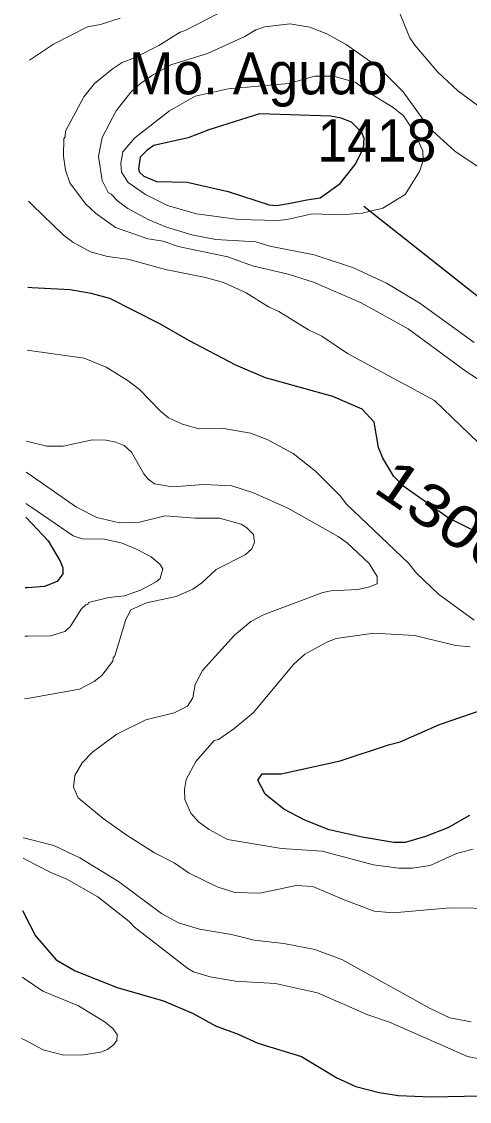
# Model space of a CAD drawing. Extents: x 598.3 to 623.2, y 6902.2 to 6930.1.
# Drawn here: x 598.405 to 599.256, y 6911.953 to 6914.004 of the extents above; entities that cross this region are included whole.
import ezdxf
from ezdxf.enums import TextEntityAlignment as Align

# ---------------------------------------------------------------- set-up
doc = ezdxf.new("R2010")
doc.units = 0
doc.header["$LTSCALE"] = 0.032
for name, color, linetype, lineweight in [('1', 7, 'Continuous', 25), ('2', 7, 'Continuous', 13), ('26', 7, 'Continuous', 25)]:
    doc.layers.add(name, color=color, linetype=linetype, lineweight=lineweight)
for name, color, linetype in [('21', 7, 'Continuous'), ('27', 7, 'Continuous'), ('61', 7, 'Continuous')]:
    doc.layers.add(name, color=color, linetype=linetype)

msp = doc.modelspace()

# ---------------------------------------------------------------- linework, layer by layer
at = {"layer": '1'}
msp.add_lwpolyline([(598.9122, 6913.6582), (598.9469, 6913.6651), (598.9727, 6913.6693), (599.0105, 6913.6961), (599.0387, 6913.7324), (599.0545, 6913.7632), (599.0563, 6913.7821), (599.0519, 6913.7933), (599.0322, 6913.8129), (599.0123, 6913.8205), (598.9919, 6913.8245), (598.8572, 6913.8285), (598.7607, 6913.798), (598.7215, 6913.7832), (598.6564, 6913.7686), (598.6433, 6913.7595), (598.6306, 6913.7464), (598.6274, 6913.724), (598.629, 6913.7176), (598.6374, 6913.7102), (598.6613, 6913.6999), (598.7199, 6913.699), (598.7976, 6913.6812), (598.8753, 6913.656), (598.8892, 6913.6545)], close=True, dxfattribs=at)
for points in [[(599.3331, 6913.0032), (599.2155, 6913.0611), (599.1295, 6913.1217), (599.1124, 6913.1398), (599.0918, 6913.1743), (599.0836, 6913.1948), (599.0748, 6913.2432), (599.0523, 6913.2675), (598.9967, 6913.2917), (598.8688, 6913.3274), (598.8122, 6913.3513), (598.7228, 6913.3978), (598.6676, 6913.4296), (598.5725, 6913.4779), (598.5373, 6913.4876), (598.4975, 6913.4942), (598.4242, 6913.4983), (598.4166, 6913.4987)], [(598.413, 6913.0626), (598.4244, 6913.0504), (598.4552, 6913.0173), (598.4784, 6912.9791), (598.4832, 6912.9661), (598.4832, 6912.9545), (598.4726, 6912.9405), (598.4485, 6912.9308), (598.4161, 6912.9284), (598.4119, 6912.9281)], [(599.2564, 6912.4958), (599.2148, 6912.4725), (599.1726, 6912.4555), (599.1343, 6912.4443), (599.1123, 6912.4443), (599.0523, 6912.4543), (598.9896, 6912.4686), (598.9432, 6912.4871), (598.9031, 6912.5076), (598.8682, 6912.5363), (598.8541, 6912.563), (598.8621, 6912.5745), (598.898, 6912.5747), (599.0104, 6912.5992), (599.1026, 6912.6302), (599.1246, 6912.6355), (599.1991, 6912.6687), (599.3027, 6912.7042)], [(598.4069, 6912.3154), (598.4206, 6912.2881), (598.4311, 6912.2671), (598.4706, 6912.2216), (598.5066, 6912.2003), (598.5865, 6912.1691), (598.6749, 6912.1433), (598.7312, 6912.1195), (598.7737, 6912.0959), (598.8164, 6912.0803), (598.8537, 6912.0632), (598.9367, 6912.0377), (599.0044, 6911.9972), (599.0404, 6911.9811), (599.0846, 6911.9694), (599.1214, 6911.9634), (599.1835, 6911.9611), (599.3103, 6911.9634)]]:
    msp.add_lwpolyline(points, dxfattribs=at)
at = {"layer": '2'}
for points in [[(598.9599, 6913.5091), (598.9117, 6913.5243), (598.844, 6913.5396), (598.7968, 6913.5567), (598.7027, 6913.5765), (598.674, 6913.5865), (598.6449, 6913.5914), (598.5834, 6913.6125), (598.5455, 6913.6401), (598.5263, 6913.6576), (598.4968, 6913.6976), (598.4881, 6913.7214), (598.4848, 6913.7482), (598.4849, 6913.782), (598.488, 6913.7851), (598.4881, 6913.7959), (598.523, 6913.8612), (598.5435, 6913.8864), (598.5771, 6913.9137), (598.596, 6913.9261), (598.6193, 6913.935), (598.6659, 6913.9587), (598.7064, 6913.9838), (598.7156, 6913.9867), (598.7997, 6914.0303)], [(599.1212, 6914.0256), (599.1427, 6913.9731), (599.1522, 6913.9589), (599.1963, 6913.9078), (599.2342, 6913.8724), (599.3103, 6913.8165)], [(598.592, 6914.0107), (598.5547, 6913.9985), (598.5303, 6913.9937), (598.4657, 6913.9613), (598.4258, 6913.9346), (598.4201, 6913.9308)], [(599.265, 6913.394), (599.1621, 6913.4687), (599.0987, 6913.507), (599.0359, 6913.536), (598.9608, 6913.5605), (598.877, 6913.5775), (598.8501, 6913.5857), (598.7741, 6913.5898), (598.7287, 6913.5988), (598.6806, 6913.6135), (598.6458, 6913.6281), (598.6066, 6913.6491), (598.588, 6913.663), (598.5754, 6913.6762), (598.5695, 6913.679), (598.5583, 6913.7022), (598.5513, 6913.7475), (598.5578, 6913.7835), (598.5849, 6913.8345), (598.6128, 6913.8698), (598.6307, 6913.8864), (598.6538, 6913.9023), (598.6888, 6913.9215), (598.7582, 6913.9433), (598.8295, 6913.9757), (598.8504, 6913.9881), (598.8672, 6913.9937), (598.915, 6913.9994), (598.9527, 6913.9936)], [(598.9527, 6913.9936), (598.9854, 6913.9805), (599.0218, 6913.9603), (599.0844, 6913.9161), (599.1301, 6913.8704), (599.1787, 6913.8024), (599.2284, 6913.758), (599.3226, 6913.6942)], [(598.4179, 6913.6626), (598.4248, 6913.6559), (598.4846, 6913.598), (598.5024, 6913.585), (598.536, 6913.5663), (598.5685, 6913.5574), (598.6067, 6913.5523), (598.6786, 6913.5331), (598.7542, 6913.5176), (598.789, 6913.508), (598.8317, 6913.4888), (598.8745, 6913.4617), (598.8936, 6913.4533), (598.9503, 6913.4184), (598.9756, 6913.4066), (599.0244, 6913.3732), (599.1898, 6913.2843), (599.2724, 6913.2052)], [(599.3075, 6913.3015), (599.25, 6913.3389), (599.1397, 6913.4205), (599.0501, 6913.4698), (598.9599, 6913.5091)], [(599.2651, 6912.8668), (599.1971, 6912.9164), (599.1555, 6912.9562), (599.1402, 6912.9749), (599.0226, 6913.0874), (599.0103, 6913.103), (598.9636, 6913.1498), (598.9214, 6913.1832), (598.872, 6913.2099), (598.84, 6913.222), (598.7892, 6913.231), (598.7417, 6913.2303), (598.7086, 6913.2396), (598.6844, 6913.2514), (598.6691, 6913.2638), (598.6288, 6913.3047), (598.6075, 6913.3213), (598.5656, 6913.3473), (598.524, 6913.3646), (598.4242, 6913.3785), (598.4156, 6913.3797)], [(598.4142, 6913.2068), (598.4295, 6913.2031), (598.4528, 6913.1975), (598.4841, 6913.1972), (598.5397, 6913.2092), (598.5658, 6913.2084), (598.5839, 6913.2052), (598.5998, 6913.1987), (598.6141, 6913.1859), (598.637, 6913.1445), (598.6455, 6913.1344), (598.6575, 6913.1258), (598.6911, 6913.1203), (598.7514, 6913.1243), (598.8043, 6913.1218), (598.8456, 6913.1089), (598.9109, 6913.0796), (599.0065, 6913.0258), (599.0235, 6913.0137), (599.0658, 6912.9747), (599.0806, 6912.9499), (599.0805, 6912.9358), (599.0646, 6912.9292), (599.0441, 6912.925), (598.993, 6912.9226), (598.9773, 6912.9195), (598.8662, 6912.8777), (598.8408, 6912.8642), (598.8094, 6912.8385), (598.7489, 6912.771), (598.7351, 6912.7444), (598.7307, 6912.719), (598.72, 6912.7032), (598.6949, 6912.6905), (598.6409, 6912.6773), (598.5857, 6912.6501), (598.5404, 6912.6163), (598.5201, 6912.596), (598.5059, 6912.5719), (598.5035, 6912.5496), (598.5122, 6912.5294), (598.5602, 6912.4898), (598.6035, 6912.4592), (598.6578, 6912.425), (598.6951, 6912.4056), (598.7237, 6912.386), (598.7765, 6912.3601), (598.81, 6912.3496), (598.8578, 6912.348), (598.9266, 6912.3625), (598.9587, 6912.361), (599.0178, 6912.3354), (599.0752, 6912.314), (599.1111, 6912.3108), (599.2186, 6912.3205), (599.3092, 6912.3188)], [(598.4102, 6912.7171), (598.419, 6912.7186), (598.5151, 6912.7355), (598.5431, 6912.7502), (598.5572, 6912.7619), (598.5785, 6912.7891), (598.5788, 6912.7953), (598.5821, 6912.7989), (598.6029, 6912.8682), (598.6128, 6912.8862), (598.6425, 6912.8994), (598.6988, 6912.9114), (598.7307, 6912.9258), (598.7473, 6912.9374), (598.7746, 6912.9629), (598.8298, 6912.9911), (598.8426, 6913.002), (598.8475, 6913.0141), (598.8455, 6913.0293), (598.8327, 6913.0426), (598.8222, 6913.049), (598.7811, 6913.0603), (598.7349, 6913.0604), (598.6776, 6913.0651), (598.6289, 6913.0527), (598.5912, 6913.0515), (598.5478, 6913.062), (598.5091, 6913.0813), (598.4258, 6913.1397), (598.4137, 6913.1482)], [(598.4132, 6913.0881), (598.4242, 6913.0806), (598.5031, 6913.0269), (598.5202, 6913.0215), (598.5623, 6913.0207), (598.5958, 6913.013), (598.6235, 6913.0019), (598.6514, 6912.9868), (598.6679, 6912.9734), (598.6733, 6912.9644), (598.6686, 6912.9462), (598.661, 6912.9395), (598.6311, 6912.9237), (598.6004, 6912.9131), (598.5709, 6912.9098), (598.532, 6912.9), (598.5307, 6912.8967), (598.527, 6912.8959), (598.5184, 6912.8874), (598.4971, 6912.8542), (598.4871, 6912.845), (598.46, 6912.837), (598.4169, 6912.8362), (598.4112, 6912.8361)], [(599.263, 6912.432), (599.2315, 6912.4233), (599.1816, 6912.4005), (599.1479, 6912.3958), (599.1218, 6912.3958), (599.0739, 6912.4022), (598.9765, 6912.4281), (598.8987, 6912.4328), (598.7962, 6912.4503), (598.7613, 6912.469), (598.7411, 6912.4835), (598.7264, 6912.5004), (598.7149, 6912.5263), (598.7148, 6912.5449), (598.7179, 6912.5639), (598.7362, 6912.5982), (598.7712, 6912.6382), (598.7794, 6912.6402), (598.8084, 6912.6602), (598.8454, 6912.6907), (598.9219, 6912.7826), (598.9435, 6912.8023), (598.9848, 6912.825), (599.0029, 6912.832), (599.0745, 6912.8418), (599.1516, 6912.8378), (599.2305, 6912.8188), (599.2577, 6912.8159)], [(599.2597, 6912.1035), (599.2189, 6912.1111), (599.1816, 6912.129), (599.0152, 6912.2215), (598.9622, 6912.2411), (598.9031, 6912.2523), (598.8469, 6912.2589), (598.8041, 6912.2694), (598.7432, 6912.2797), (598.7034, 6912.292), (598.6707, 6912.3095), (598.589, 6912.37), (598.5159, 6912.415), (598.466, 6912.4387), (598.4112, 6912.4525), (598.408, 6912.4533)], [(598.4077, 6912.4148), (598.4139, 6912.4116), (598.4591, 6912.3883), (598.4911, 6912.3748), (598.5496, 6912.3414), (598.6094, 6912.2945), (598.6198, 6912.2834), (598.7207, 6912.205), (598.7315, 6912.1988), (598.7632, 6912.1889), (598.8112, 6912.181), (598.8874, 6912.1764), (598.9671, 6912.1586), (599.0628, 6912.1169), (599.104, 6912.103), (599.2528, 6912.0378), (599.3137, 6912.0257)], [(598.4049, 6912.0722), (598.4129, 6912.068), (598.446, 6912.0504), (598.4849, 6912.0403), (598.5229, 6912.0412), (598.5547, 6912.0461), (598.5681, 6912.0513), (598.5798, 6912.0601), (598.5857, 6912.0682), (598.5867, 6912.0799), (598.5781, 6912.0911), (598.5635, 6912.1033), (598.5131, 6912.1338), (598.4451, 6912.1621), (598.4096, 6912.1861), (598.4059, 6912.1886)]]:
    msp.add_lwpolyline(points, dxfattribs=at)
msp.add_lwpolyline([(599.1339, 6913.6752), (599.1615, 6913.7193), (599.1681, 6913.7397), (599.1677, 6913.7582), (599.1501, 6913.7964), (599.1309, 6913.825), (599.1111, 6913.8408), (599.0634, 6913.8696), (599.0405, 6913.8881), (598.9983, 6913.9005), (598.9622, 6913.9004), (598.9129, 6913.8865), (598.7976, 6913.8763), (598.735, 6913.862), (598.6861, 6913.8344), (598.6199, 6913.7828), (598.5974, 6913.7564), (598.5934, 6913.7349), (598.595, 6913.7179), (598.6078, 6913.6984), (598.6403, 6913.6756), (598.6822, 6913.6548), (598.7374, 6913.639), (598.8181, 6913.6278), (598.8906, 6913.6262), (598.9094, 6913.6278), (598.9574, 6913.639), (599.012, 6913.6366), (599.0522, 6913.6397), (599.0917, 6913.6495)], close=True, dxfattribs=at)
at = {"layer": '26'}
msp.add_lwpolyline([(599.0555, 6913.6532), (599.6413, 6913.1902), (600.4019, 6912.68), (600.9641, 6912.3824), (601.668, 6911.9525)], dxfattribs=at)

# ---------------------------------------------------------------- texts
at = {"layer": '21', "width": 0.95}
msp.add_text('1418', height=0.08, dxfattribs=at).set_placement((598.9672, 6913.7381))
at = {"layer": '27', "width": 0.95}
msp.add_text('Mo. Agudo', height=0.08, dxfattribs=at).set_placement((598.8545, 6913.8657), align=Align.CENTER)
at = {"layer": '61', "width": 1.2}
msp.add_text('1300', height=0.08, rotation=325.491, dxfattribs=at).set_placement((599.1881, 6913.0314), align=Align.CENTER)

doc.saveas('drawing.dxf')
